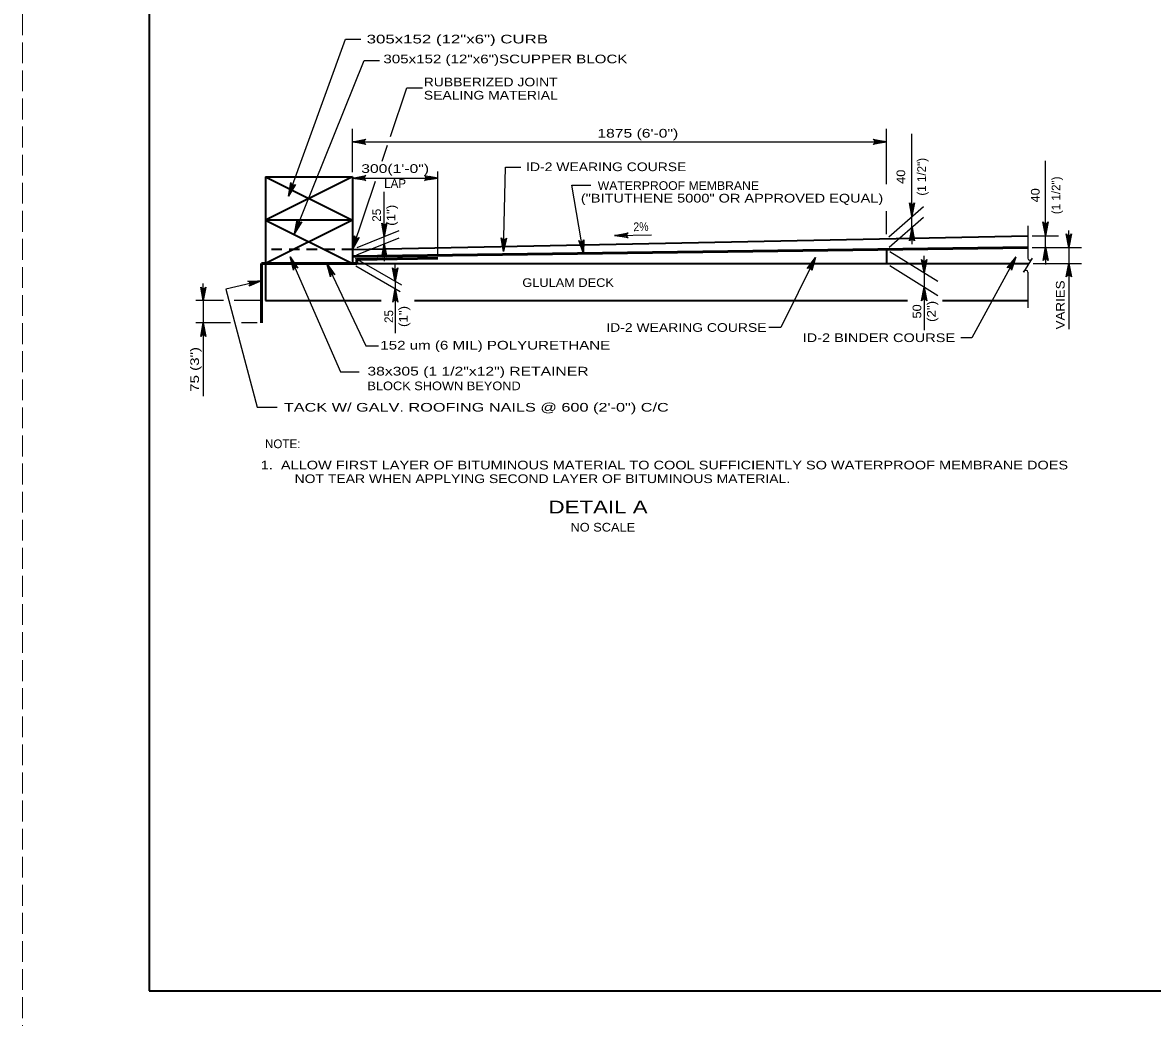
# Model space of a CAD drawing. Extents: x -11 to 79, y -154 to 0.
# Drawn here: x 0 to 15.61, y -87.62 to -73.87 of the extents above; entities that cross this region are included whole.
import ezdxf
from ezdxf.enums import TextEntityAlignment as Align

# ---------------------------------------------------------------- set-up
doc = ezdxf.new("R2010")
doc.units = 0
doc.header["$LTSCALE"] = 0.048
doc.linetypes.add('LONG_DASHED', pattern=[7.5, 6, -1.5])
doc.linetypes.add('MEDIUM_DASHED', pattern=[4.5, 3, -1.5])
for name, color, linetype, lineweight in [('1', 7, 'Continuous', 25), ('2', 7, 'Continuous', 35), ('3', 7, 'Continuous', 25), ('4', 7, 'Continuous', 25), ('63', 7, 'LONG_DASHED', 13)]:
    doc.layers.add(name, color=color, linetype=linetype, lineweight=lineweight)

msp = doc.modelspace()

# ---------------------------------------------------------------- hatches: boundary and pattern name
at = {"layer": '4'}
for points in [[(4.67533, -75.502), (4.67533, -75.54133), (4.55717, -75.52167)], [(11.82092, -75.502), (11.82092, -75.54133), (11.93908, -75.52167)], [(4.67533, -76.00233), (4.67533, -76.04167), (4.55717, -76.022)], [(5.62017, -76.00233), (5.62017, -76.04167), (5.73825, -76.022)], [(3.67383, -76.27258), (3.67658, -76.26858), (3.67433, -76.26775)], [(12.27, -76.433), (12.30933, -76.433), (12.28967, -76.55108)], [(3.75675, -76.78625), (3.75967, -76.78233), (3.75742, -76.78142)], [(4.97667, -76.71758), (5.016, -76.71758), (4.99633, -76.83567)], [(12.27, -76.81683), (12.30933, -76.81683), (12.28967, -76.69875)], [(14.116, -76.70283), (14.15542, -76.70283), (14.13575, -76.821)], [(4.97667, -77.05225), (5.016, -77.05225), (4.99633, -76.93408)], [(7.75283, -77.0635), (7.74233, -76.94542), (7.72292, -76.94875)], [(14.43692, -76.8635), (14.47633, -76.8635), (14.45658, -76.98158)], [(3.69875, -77.10933), (3.69958, -77.11417), (3.70175, -77.11325)], [(4.55717, -77.00767), (4.55983, -77.00358), (4.55758, -77.00275)], [(6.64492, -77.03692), (6.64617, -77.03225), (6.64383, -77.03217)], [(10.95683, -77.11867), (10.95367, -77.12242), (10.95575, -77.1235)], [(13.72283, -77.114), (13.7195, -77.11758), (13.72158, -77.11867)], [(14.116, -77.09975), (14.15542, -77.09975), (14.13575, -76.98158)], [(4.20442, -77.2045), (4.20542, -77.20925), (4.20758, -77.20825)], [(12.43783, -77.21558), (12.47725, -77.21558), (12.45758, -77.33375)], [(14.43692, -77.32258), (14.47633, -77.32258), (14.45658, -77.2045)], [(5.12883, -77.33125), (5.16825, -77.33125), (5.14858, -77.44933)], [(3.30217, -77.44067), (3.29733, -77.44067), (3.29783, -77.44292)], [(5.12883, -77.66592), (5.16825, -77.66592), (5.14858, -77.54783)], [(12.43783, -77.64867), (12.47725, -77.64867), (12.45758, -77.53058)], [(2.47583, -77.59817), (2.51517, -77.59817), (2.4955, -77.71633)], [(2.47583, -78.14275), (2.51517, -78.14275), (2.4955, -78.02467)]]:
    msp.add_hatch(color=256, dxfattribs=at).paths.add_polyline_path(points)

# ---------------------------------------------------------------- linework, layer by layer
at = {"layer": '1', "lineweight": 35}
msp.add_lwpolyline([(1.75, -87.25), (33.25, -87.25), (33.25, -66.75), (1.75, -66.75)], close=True, dxfattribs=at)
at = {"layer": '2', "lineweight": 25}
for p, q in [((8.181, -76.81792), (8.6895, -76.80483)), ((13.89058, -76.68117), (13.89058, -77.128)), ((13.89058, -77.32225), (13.89058, -77.81425))]:
    msp.add_line(p, q, dxfattribs=at)
msp.add_lwpolyline([(13.94358, -77.14225), (13.95108, -77.13025), (13.83008, -77.32267), (13.83825, -77.30983)], dxfattribs=at)
for centre, start, end in [((13.91897, -77.12803), 180, 330), ((13.86227, -77.32492), 5.32859, 147.86724)]:
    msp.add_arc(centre, 0.02841, start, end, dxfattribs=at)
at = {"layer": '3', "lineweight": 35}
for p, q in [((3.35642, -76.00367), (3.35642, -77.71633)), ((3.35642, -76.00367), (4.55717, -76.00367)), ((3.35642, -76.00367), (4.55717, -76.60408)), ((4.55717, -76.00367), (4.55717, -77.2045)), ((4.55717, -76.60408), (3.35642, -76.60408)), ((4.55717, -76.60408), (3.35642, -77.2045)), ((4.55717, -77.00767), (13.89058, -76.821)), ((11.93908, -77.00767), (11.93908, -77.2045)), ((4.61817, -77.2045), (13.90442, -77.2045)), ((3.35642, -77.71633), (4.95692, -77.71633)), ((5.41475, -77.71633), (12.229, -77.71633)), ((12.70933, -77.71633), (13.89058, -77.71633))]:
    msp.add_line(p, q, dxfattribs=at)
at = {"layer": '3', "linetype": 'MEDIUM_DASHED', "lineweight": 35}
msp.add_line((4.55717, -77.00767), (3.35642, -77.00767), dxfattribs=at)
at = {"layer": '3', "lineweight": 53}
for p, q in [((4.55717, -77.10608), (13.89058, -76.98158)), ((3.30217, -77.2045), (3.30267, -78.02467)), ((3.30217, -77.2045), (4.61817, -77.2045)), ((4.61817, -77.14592), (5.73825, -77.131)), ((4.61817, -77.14592), (4.61817, -77.2045))]:
    msp.add_line(p, q, dxfattribs=at)
at = {"layer": '3', "lineweight": 35}
msp.add_lwpolyline([(4.55717, -76.00367), (3.35642, -76.60408), (4.55717, -77.2045)], dxfattribs=at)
at = {"layer": '4'}
for p, q in [((3.67383, -76.27258), (4.46142, -74.10192)), ((4.46142, -74.10192), (4.67517, -74.10192)), ((3.75675, -76.78625), (4.71842, -74.40017)), ((4.71842, -74.40017), (4.93217, -74.40017)), ((5.08408, -75.44908), (5.31167, -74.77592)), ((5.31167, -74.77592), (5.52542, -74.77592)), ((4.55717, -75.94217), (4.55717, -75.3445)), ((11.93908, -76.1075), (11.93908, -75.3445)), ((4.55717, -75.52167), (11.93908, -75.52167)), ((12.28967, -76.433), (12.28967, -75.41225)), ((4.96875, -75.79025), (5.04342, -75.56925)), ((14.13575, -76.70283), (14.13575, -75.78608)), ((4.55717, -76.022), (5.73825, -76.022)), ((5.73825, -77.06942), (5.73825, -75.93117)), ((6.64492, -77.03692), (6.67292, -75.87417)), ((6.67292, -75.87417), (6.88667, -75.87417)), ((4.55717, -77.00767), (4.87575, -76.06517)), ((7.75283, -77.0635), (7.58942, -76.1225)), ((7.58942, -76.1225), (7.85058, -76.1225)), ((4.99633, -76.71758), (4.99633, -76.21333)), ((11.93908, -76.7985), (11.93908, -76.48042)), ((11.97025, -76.83283), (12.44742, -76.41417)), ((11.9745, -76.97658), (12.44708, -76.56183)), ((12.28967, -76.69875), (12.28967, -76.55108)), ((4.62508, -76.98042), (5.20483, -76.74775)), ((14.45658, -76.8635), (14.45658, -76.74542)), ((4.6175, -77.08183), (5.20483, -76.84625)), ((4.99633, -76.93408), (4.99633, -76.83567)), ((12.28967, -76.81683), (12.28967, -76.93492)), ((13.95208, -76.821), (14.31292, -76.821)), ((14.13575, -76.98158), (14.13575, -76.821)), ((3.69875, -77.10933), (4.39167, -78.69992)), ((4.99633, -77.05225), (4.99633, -77.17033)), ((10.95683, -77.11867), (10.47783, -78.08733)), ((11.98467, -77.036), (12.64892, -77.44875)), ((12.45758, -77.21558), (12.45758, -77.0975)), ((13.72283, -77.114), (13.11867, -78.22858)), ((13.95208, -76.98158), (14.63375, -76.98158)), ((13.95208, -76.98158), (14.31292, -76.98158)), ((14.13575, -77.09975), (14.13575, -77.21783)), ((14.45658, -76.98158), (14.45658, -77.2045)), ((4.20442, -77.2045), (4.74483, -78.34117)), ((4.5965, -77.12892), (5.23442, -77.49908)), ((4.60667, -77.23325), (5.21917, -77.58858)), ((5.14858, -77.33125), (5.14858, -77.21317)), ((11.982, -77.23117), (12.64892, -77.64558)), ((13.96592, -77.2045), (14.63375, -77.2045)), ((12.45758, -77.33375), (12.45758, -77.53058)), ((14.45658, -77.32258), (14.45658, -78.11)), ((2.4955, -77.59817), (2.4955, -77.48008)), ((5.14858, -77.44933), (5.14858, -77.54783)), ((2.77417, -77.71633), (2.3935, -77.71633)), ((2.4955, -77.71633), (2.4955, -78.02467)), ((3.29492, -77.71633), (2.92458, -77.71633)), ((5.14858, -77.66592), (5.14858, -78.16417)), ((12.45758, -77.64867), (12.45758, -78.12533)), ((2.87442, -78.02467), (2.3935, -78.02467)), ((3.24108, -78.02467), (3.02483, -78.02467)), ((2.4955, -78.14275), (2.4955, -79.03558)), ((10.47783, -78.08733), (10.311, -78.08733)), ((4.74483, -78.34117), (4.92017, -78.34117)), ((13.11867, -78.22858), (12.96683, -78.22858)), ((4.39167, -78.69992), (4.64967, -78.69992))]:
    msp.add_line(p, q, dxfattribs=at)
for points in [[(4.55717, -75.52167), (4.74358, -75.48675), (4.72925, -75.49667), (4.72183, -75.50917), (4.71967, -75.52167), (4.72183, -75.53417), (4.72925, -75.54667), (4.74358, -75.55658), (4.55717, -75.52167), (4.72925, -75.54667), (4.72183, -75.53417), (4.55717, -75.52167), (4.71967, -75.52167), (4.72183, -75.50917), (4.55717, -75.52167), (4.72925, -75.49667)], [(11.93908, -75.52167), (11.75267, -75.55658), (11.767, -75.54667), (11.77442, -75.53417), (11.77658, -75.52167), (11.77442, -75.50917), (11.767, -75.49667), (11.75267, -75.48675), (11.93908, -75.52167), (11.767, -75.49667), (11.77442, -75.50917), (11.93908, -75.52167), (11.77658, -75.52167), (11.77442, -75.53417), (11.93908, -75.52167), (11.767, -75.54667)], [(4.55717, -76.022), (4.74358, -75.98708), (4.72925, -75.997), (4.72183, -76.0095), (4.71967, -76.022), (4.72183, -76.0345), (4.72925, -76.047), (4.74358, -76.05692), (4.55717, -76.022), (4.72925, -76.047), (4.72183, -76.0345), (4.55717, -76.022), (4.71967, -76.022), (4.72183, -76.0095), (4.55717, -76.022), (4.72925, -75.997)], [(5.73825, -76.022), (5.55183, -76.05692), (5.56617, -76.047), (5.57358, -76.0345), (5.57575, -76.022), (5.57358, -76.0095), (5.56617, -75.997), (5.55183, -75.98708), (5.73825, -76.022), (5.56617, -75.997), (5.57358, -76.0095), (5.73825, -76.022), (5.57575, -76.022), (5.57358, -76.0345), (5.73825, -76.022), (5.56617, -76.047)], [(3.67383, -76.27258), (3.70458, -76.08542), (3.709, -76.10233), (3.71825, -76.11358), (3.72925, -76.11983), (3.74175, -76.12208), (3.756, -76.11942), (3.77025, -76.10925), (3.67383, -76.27258), (3.756, -76.11942), (3.74175, -76.12208), (3.67383, -76.27258), (3.72925, -76.11983), (3.71825, -76.11358), (3.67383, -76.27258), (3.709, -76.10233)], [(12.28958, -76.55042), (12.25458, -76.364), (12.26458, -76.37833), (12.27708, -76.38575), (12.28958, -76.38792), (12.30208, -76.38575), (12.31458, -76.37833), (12.3245, -76.364), (12.28958, -76.55042), (12.31458, -76.37833), (12.30208, -76.38575), (12.28958, -76.55042), (12.28958, -76.38792), (12.27708, -76.38575), (12.28958, -76.55042), (12.26458, -76.37833)], [(3.75675, -76.78625), (3.794, -76.60025), (3.79792, -76.61733), (3.80667, -76.62883), (3.8175, -76.6355), (3.82992, -76.63825), (3.84425, -76.636), (3.85883, -76.62642), (3.75675, -76.78625), (3.84425, -76.636), (3.82992, -76.63825), (3.75675, -76.78625), (3.8175, -76.6355), (3.80667, -76.62883), (3.75675, -76.78625), (3.79792, -76.61733)], [(4.99708, -76.83108), (4.96217, -76.64467), (4.97208, -76.65908), (4.98458, -76.6665), (4.99708, -76.66858), (5.00958, -76.6665), (5.02208, -76.65908), (5.03208, -76.64467), (4.99708, -76.83108), (5.02208, -76.65908), (5.00958, -76.6665), (4.99708, -76.83108), (4.99708, -76.66858), (4.98458, -76.6665), (4.99708, -76.83108), (4.97208, -76.65908)], [(14.13442, -76.81317), (14.0995, -76.62675), (14.10942, -76.64117), (14.12192, -76.64858), (14.13442, -76.65067), (14.14692, -76.64858), (14.15942, -76.64117), (14.16942, -76.62675), (14.13442, -76.81317), (14.15942, -76.64117), (14.14692, -76.64858), (14.13442, -76.81317), (14.13442, -76.65067), (14.12192, -76.64858), (14.13442, -76.81317), (14.10942, -76.64117)], [(8.181, -76.81792), (8.3665, -76.77817), (8.35233, -76.7885), (8.34525, -76.80117), (8.34342, -76.81375), (8.34592, -76.82617), (8.35367, -76.8385), (8.36825, -76.84808), (8.181, -76.81792), (8.35367, -76.8385), (8.34592, -76.82617), (8.181, -76.81792), (8.34342, -76.81375), (8.34525, -76.80117), (8.181, -76.81792), (8.35233, -76.7885)], [(12.29058, -76.70433), (12.32558, -76.89075), (12.31558, -76.87642), (12.30308, -76.869), (12.29058, -76.86683), (12.27808, -76.869), (12.26558, -76.87642), (12.25567, -76.89075), (12.29058, -76.70433), (12.26558, -76.87642), (12.27808, -76.869), (12.29058, -76.70433), (12.29058, -76.86683), (12.30308, -76.869), (12.29058, -76.70433), (12.31558, -76.87642)], [(14.45658, -76.98158), (14.42167, -76.79517), (14.43158, -76.8095), (14.44408, -76.81692), (14.45658, -76.81908), (14.46908, -76.81692), (14.48158, -76.8095), (14.4915, -76.79517), (14.45658, -76.98158), (14.48158, -76.8095), (14.46908, -76.81692), (14.45658, -76.98158), (14.45658, -76.81908), (14.44408, -76.81692), (14.45658, -76.98158), (14.43158, -76.8095)], [(4.55717, -77.00767), (4.58375, -76.81992), (4.58858, -76.83667), (4.59808, -76.84767), (4.60925, -76.85375), (4.62175, -76.85567), (4.63592, -76.85267), (4.65, -76.84225), (4.55717, -77.00767), (4.63592, -76.85267), (4.62175, -76.85567), (4.55717, -77.00767), (4.60925, -76.85375), (4.59808, -76.84767), (4.55717, -77.00767), (4.58858, -76.83667)], [(4.99708, -76.92958), (5.032, -77.116), (5.02208, -77.10167), (5.00958, -77.09425), (4.99708, -77.09208), (4.98458, -77.09425), (4.97208, -77.10167), (4.96217, -77.116), (4.99708, -76.92958), (4.97208, -77.10167), (4.98458, -77.09425), (4.99708, -76.92958), (4.99708, -77.09208), (5.00958, -77.09425), (4.99708, -76.92958), (5.02208, -77.10167)], [(6.64492, -77.03692), (6.6145, -76.84975), (6.62408, -76.86433), (6.63642, -76.872), (6.64883, -76.8745), (6.66142, -76.87258), (6.67408, -76.8655), (6.68433, -76.85142), (6.64492, -77.03692), (6.67408, -76.8655), (6.66142, -76.87258), (6.64492, -77.03692), (6.64883, -76.8745), (6.63642, -76.872), (6.64492, -77.03692), (6.62408, -76.86433)], [(7.75283, -77.0635), (7.6865, -76.88583), (7.69875, -76.89825), (7.71233, -76.90342), (7.725, -76.90342), (7.737, -76.89917), (7.748, -76.88975), (7.75533, -76.87383), (7.75283, -77.0635), (7.748, -76.88975), (7.737, -76.89917), (7.75283, -77.0635), (7.725, -76.90342), (7.71233, -76.90342), (7.75283, -77.0635), (7.69875, -76.89825)], [(3.69875, -77.10933), (3.80525, -77.26625), (3.79042, -77.25708), (3.776, -77.25525), (3.76367, -77.25833), (3.75308, -77.26525), (3.74458, -77.27708), (3.74117, -77.29417), (3.69875, -77.10933), (3.74458, -77.27708), (3.75308, -77.26525), (3.69875, -77.10933), (3.76367, -77.25833), (3.776, -77.25525), (3.69875, -77.10933), (3.79042, -77.25708)], [(10.95683, -77.11867), (10.9055, -77.30125), (10.903, -77.284), (10.89508, -77.27183), (10.88483, -77.26433), (10.87267, -77.26075), (10.85817, -77.26183), (10.84283, -77.27025), (10.95683, -77.11867), (10.85817, -77.26183), (10.87267, -77.26075), (10.95683, -77.11867), (10.88483, -77.26433), (10.89508, -77.27183), (10.95683, -77.11867), (10.903, -77.284)], [(13.72283, -77.114), (13.66475, -77.29458), (13.66283, -77.27717), (13.65533, -77.26467), (13.64542, -77.25683), (13.63342, -77.25275), (13.61883, -77.25333), (13.60325, -77.26125), (13.72283, -77.114), (13.61883, -77.25333), (13.63342, -77.25275), (13.72283, -77.114), (13.64542, -77.25683), (13.65533, -77.26467), (13.72283, -77.114), (13.66283, -77.27717)], [(14.13575, -76.974), (14.17067, -77.16042), (14.16075, -77.146), (14.14825, -77.13858), (14.13575, -77.1365), (14.12325, -77.13858), (14.11075, -77.146), (14.10083, -77.16042), (14.13575, -76.974), (14.11075, -77.146), (14.12325, -77.13858), (14.13575, -76.974), (14.13575, -77.1365), (14.14825, -77.13858), (14.13575, -76.974), (14.16075, -77.146)], [(4.20442, -77.2045), (4.316, -77.35783), (4.30083, -77.34917), (4.28642, -77.34783), (4.27417, -77.35125), (4.26383, -77.35858), (4.25567, -77.37058), (4.25292, -77.38783), (4.20442, -77.2045), (4.25567, -77.37058), (4.26383, -77.35858), (4.20442, -77.2045), (4.27417, -77.35125), (4.28642, -77.34783), (4.20442, -77.2045), (4.30083, -77.34917)], [(5.1485, -77.45), (5.1135, -77.26358), (5.1235, -77.27792), (5.136, -77.28533), (5.1485, -77.2875), (5.161, -77.28533), (5.1735, -77.27792), (5.18342, -77.26358), (5.1485, -77.45), (5.1735, -77.27792), (5.161, -77.28533), (5.1485, -77.45), (5.1485, -77.2875), (5.136, -77.28533), (5.1485, -77.45), (5.1235, -77.27792)], [(12.45758, -77.33375), (12.42267, -77.14733), (12.43258, -77.16167), (12.44508, -77.16908), (12.45758, -77.17125), (12.47008, -77.16908), (12.48258, -77.16167), (12.4925, -77.14733), (12.45758, -77.33375), (12.48258, -77.16167), (12.47008, -77.16908), (12.45758, -77.33375), (12.45758, -77.17125), (12.44508, -77.16908), (12.45758, -77.33375), (12.43258, -77.16167)], [(14.45658, -77.2025), (14.4915, -77.38892), (14.48158, -77.37458), (14.46908, -77.36717), (14.45658, -77.365), (14.44408, -77.36717), (14.43158, -77.37458), (14.42167, -77.38892), (14.45658, -77.2025), (14.43158, -77.37458), (14.44408, -77.36717), (14.45658, -77.2025), (14.45658, -77.365), (14.46908, -77.36717), (14.45658, -77.2025), (14.48158, -77.37458)], [(2.4955, -77.71633), (2.46058, -77.52992), (2.4705, -77.54425), (2.483, -77.55167), (2.4955, -77.55383), (2.508, -77.55167), (2.5205, -77.54425), (2.53042, -77.52992), (2.4955, -77.71633), (2.5205, -77.54425), (2.508, -77.55167), (2.4955, -77.71633), (2.4955, -77.55383), (2.483, -77.55167), (2.4955, -77.71633), (2.4705, -77.54425)], [(3.30217, -77.44067), (2.8075, -77.55533), (3.242, -79.18867), (3.51775, -79.18867)], [(3.30217, -77.44067), (3.1285, -77.51683), (3.14025, -77.50392), (3.14458, -77.49008), (3.14383, -77.47733), (3.139, -77.46567), (3.12892, -77.45517), (3.11267, -77.44875), (3.30217, -77.44067), (3.12892, -77.45517), (3.139, -77.46567), (3.30217, -77.44067), (3.14383, -77.47733), (3.14458, -77.49008), (3.30217, -77.44067), (3.14025, -77.50392)], [(5.14867, -77.54858), (5.18367, -77.735), (5.17367, -77.72058), (5.16117, -77.71317), (5.14867, -77.71108), (5.13617, -77.71317), (5.12367, -77.72058), (5.11375, -77.735), (5.14867, -77.54858), (5.12367, -77.72058), (5.13617, -77.71317), (5.14867, -77.54858), (5.14867, -77.71108), (5.16117, -77.71317), (5.14867, -77.54858), (5.17367, -77.72058)], [(12.45758, -77.53058), (12.4925, -77.717), (12.48258, -77.70267), (12.47008, -77.69525), (12.45758, -77.69308), (12.44508, -77.69525), (12.43258, -77.70267), (12.42267, -77.717), (12.45758, -77.53058), (12.43258, -77.70267), (12.44508, -77.69525), (12.45758, -77.53058), (12.45758, -77.69308), (12.47008, -77.69525), (12.45758, -77.53058), (12.48258, -77.70267)], [(2.4955, -78.02467), (2.53042, -78.21108), (2.5205, -78.19675), (2.508, -78.18933), (2.4955, -78.18717), (2.483, -78.18933), (2.4705, -78.19675), (2.46058, -78.21108), (2.4955, -78.02467), (2.4705, -78.19675), (2.483, -78.18933), (2.4955, -78.02467), (2.4955, -78.18717), (2.508, -78.18933), (2.4955, -78.02467), (2.5205, -78.19675)]]:
    msp.add_lwpolyline(points, dxfattribs=at)
for points in [[(4.67533, -75.502), (4.67533, -75.54133), (4.55717, -75.52167)], [(11.82092, -75.502), (11.82092, -75.54133), (11.93908, -75.52167)], [(4.67533, -76.00233), (4.67533, -76.04167), (4.55717, -76.022)], [(5.62017, -76.00233), (5.62017, -76.04167), (5.73825, -76.022)], [(3.67383, -76.27258), (3.67658, -76.26858), (3.67433, -76.26775)], [(12.27, -76.433), (12.30933, -76.433), (12.28967, -76.55108)], [(3.75675, -76.78625), (3.75967, -76.78233), (3.75742, -76.78142)], [(4.97667, -76.71758), (5.016, -76.71758), (4.99633, -76.83567)], [(12.27, -76.81683), (12.30933, -76.81683), (12.28967, -76.69875)], [(14.116, -76.70283), (14.15542, -76.70283), (14.13575, -76.821)], [(4.97667, -77.05225), (5.016, -77.05225), (4.99633, -76.93408)], [(7.75283, -77.0635), (7.74233, -76.94542), (7.72292, -76.94875)], [(14.43692, -76.8635), (14.47633, -76.8635), (14.45658, -76.98158)], [(3.69875, -77.10933), (3.69958, -77.11417), (3.70175, -77.11325)], [(4.55717, -77.00767), (4.55983, -77.00358), (4.55758, -77.00275)], [(6.64492, -77.03692), (6.64617, -77.03225), (6.64383, -77.03217)], [(10.95683, -77.11867), (10.95367, -77.12242), (10.95575, -77.1235)], [(13.72283, -77.114), (13.7195, -77.11758), (13.72158, -77.11867)], [(14.116, -77.09975), (14.15542, -77.09975), (14.13575, -76.98158)], [(4.20442, -77.2045), (4.20542, -77.20925), (4.20758, -77.20825)], [(12.43783, -77.21558), (12.47725, -77.21558), (12.45758, -77.33375)], [(14.43692, -77.32258), (14.47633, -77.32258), (14.45658, -77.2045)], [(5.12883, -77.33125), (5.16825, -77.33125), (5.14858, -77.44933)], [(3.30217, -77.44067), (3.29733, -77.44067), (3.29783, -77.44292)], [(5.12883, -77.66592), (5.16825, -77.66592), (5.14858, -77.54783)], [(12.43783, -77.64867), (12.47725, -77.64867), (12.45758, -77.53058)], [(2.47583, -77.59817), (2.51517, -77.59817), (2.4955, -77.71633)], [(2.47583, -78.14275), (2.51517, -78.14275), (2.4955, -78.02467)]]:
    msp.add_lwpolyline(points, close=True, dxfattribs=at)
at = {"layer": '63'}
msp.add_lwpolyline([(0, -88), (34, -88), (34, -66), (0, -66)], close=True, dxfattribs=at)

# ---------------------------------------------------------------- texts
at = {"layer": '4'}
for s, width, p in [('305x152 (12"x6") CURB', 1.45, (4.75425, -74.16233)), ('305x152 (12"x6")SCUPPER BLOCK', 1.3, (4.98567, -74.43692)), ('RUBBERIZED JOINT', 1.2, (5.54283, -74.7555)), ('SEALING MATERIAL', 1.2, (5.5445, -74.93758)), ('ID-2 WEARING COURSE', 1.2, (6.95733, -75.92675)), ('WATERPROOF MEMBRANE', 1.05, (7.94725, -76.18625)), ('("BITUTHENE 5000" OR APPROVED EQUAL)', 1.25, (7.71425, -76.36025)), ('GLULAM DECK', 1.1, (6.9055, -77.52717)), ('152 um (6 MIL) POLYURETHANE', 1.3, (4.94333, -78.39158)), ('38x305 (1 1/2"x12") RETAINER', 1.35, (4.76467, -78.75033)), ('BLOCK SHOWN BEYOND', 1.1, (4.76467, -78.95367)), ('TACK W/ GALV. ROOFING NAILS @ 600 (2\'-0") C/C', 1.4, (3.60942, -79.2495)), ('1.  ALLOW FIRST LAYER OF BITUMINOUS MATERIAL TO COOL SUFFICIENTLY SO WATERPROOF MEMBRANE DOES ', 1.25, (3.29083, -80.04783)), ('NOT TEAR WHEN APPLYING SECOND LAYER OF BITUMINOUS MATERIAL.', 1.2, (3.75867, -80.23658)), ('NO SCALE', 1.1, (7.57142, -80.9065))]:
    msp.add_text(s, height=0.12, dxfattribs=dict(at, width=width)).set_placement(p)
for s, height, width, p in [('1875 (6\'-0")', 0.12, 1.35, (8.50075, -75.46333)), ('300(1\'-0")', 0.12, 1.35, (5.14779, -75.95133)), ('DETAIL A', 0.1772, 1.3, (7.95204, -80.65625))]:
    msp.add_text(s, height=height, dxfattribs=dict(at, width=width)).set_placement(p, align=Align.CENTER)
for s, p in [('(1 1/2")', (12.48233, -76.00471)), ('(1 1/2")', (14.33975, -76.26104)), ('25', (4.95183, -76.53663)), ('25', (5.12017, -77.93487))]:
    msp.add_text(s, height=0.12, rotation=90, dxfattribs=at).set_placement(p, align=Align.CENTER)
for s, width, p in [('40', 1.1, (12.19567, -76.00475)), ('40', 1.1, (14.05308, -76.26108)), ('(1")', 1.15, (5.15183, -76.53663)), ('VARIES', 1.15, (14.3985, -77.77525)), ('(2")', 1.15, (12.618, -77.86504)), ('(1")', 1.15, (5.32017, -77.93487)), ('50', 1.1, (12.418, -77.86508)), ('75 (3")', 1.3, (2.43733, -78.66662))]:
    msp.add_text(s, height=0.12, rotation=90, dxfattribs=dict(at, width=width)).set_placement(p, align=Align.CENTER)
msp.add_text('LAP', height=0.12, dxfattribs=at).set_placement((5.14779, -76.1575), align=Align.CENTER)
at = {"layer": '4', "width": 0.9}
msp.add_text('2%', height=0.12, rotation=1.504, dxfattribs=at).set_placement((8.44192, -76.75667))
at = {"layer": '4'}
for s, width, p in [('ID-2 WEARING COURSE', 1.2, (10.27967, -78.14725)), ('ID-2 BINDER COURSE', 1.25, (12.88567, -78.2885))]:
    msp.add_text(s, height=0.12, dxfattribs=dict(at, width=width)).set_placement(p, align=Align.RIGHT)
msp.add_text('NOTE:', height=0.12, dxfattribs=at).set_placement((3.34942, -79.75425))

doc.saveas('drawing.dxf')
